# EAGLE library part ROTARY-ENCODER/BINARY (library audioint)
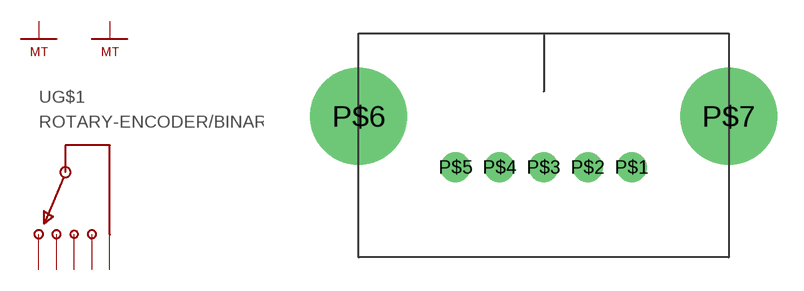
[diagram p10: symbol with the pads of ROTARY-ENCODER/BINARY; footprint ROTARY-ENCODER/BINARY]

Designator prefix -; gates G$1=ROTARY-ENCODER/BINARY G$2=MECHANICAL G$3=MECHANICAL

## ROTARY-ENCODER/BINARYALPHA  [ROTARY-ENCODER/BINARY]
P$1  G$1:P$1
P$2  G$1:P$2
P$3  G$1:P$3
P$4  G$1:P$4
P$5  G$1:P$5
P$6  G$2:MT  pas
P$7  G$3:MT  pas

## Footprint ROTARY-ENCODER/BINARY (pad centres in mm)
drill 1.092 pad 1.7 round: P$1 5,0; P$2 2.5,0; P$3 0,0; P$4 -2.5,0; P$5 -5,0
drill 4.115 pad 5.5 round: P$6 -10.5,2.9; P$7 10.5,2.9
